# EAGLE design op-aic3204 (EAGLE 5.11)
PID: 827
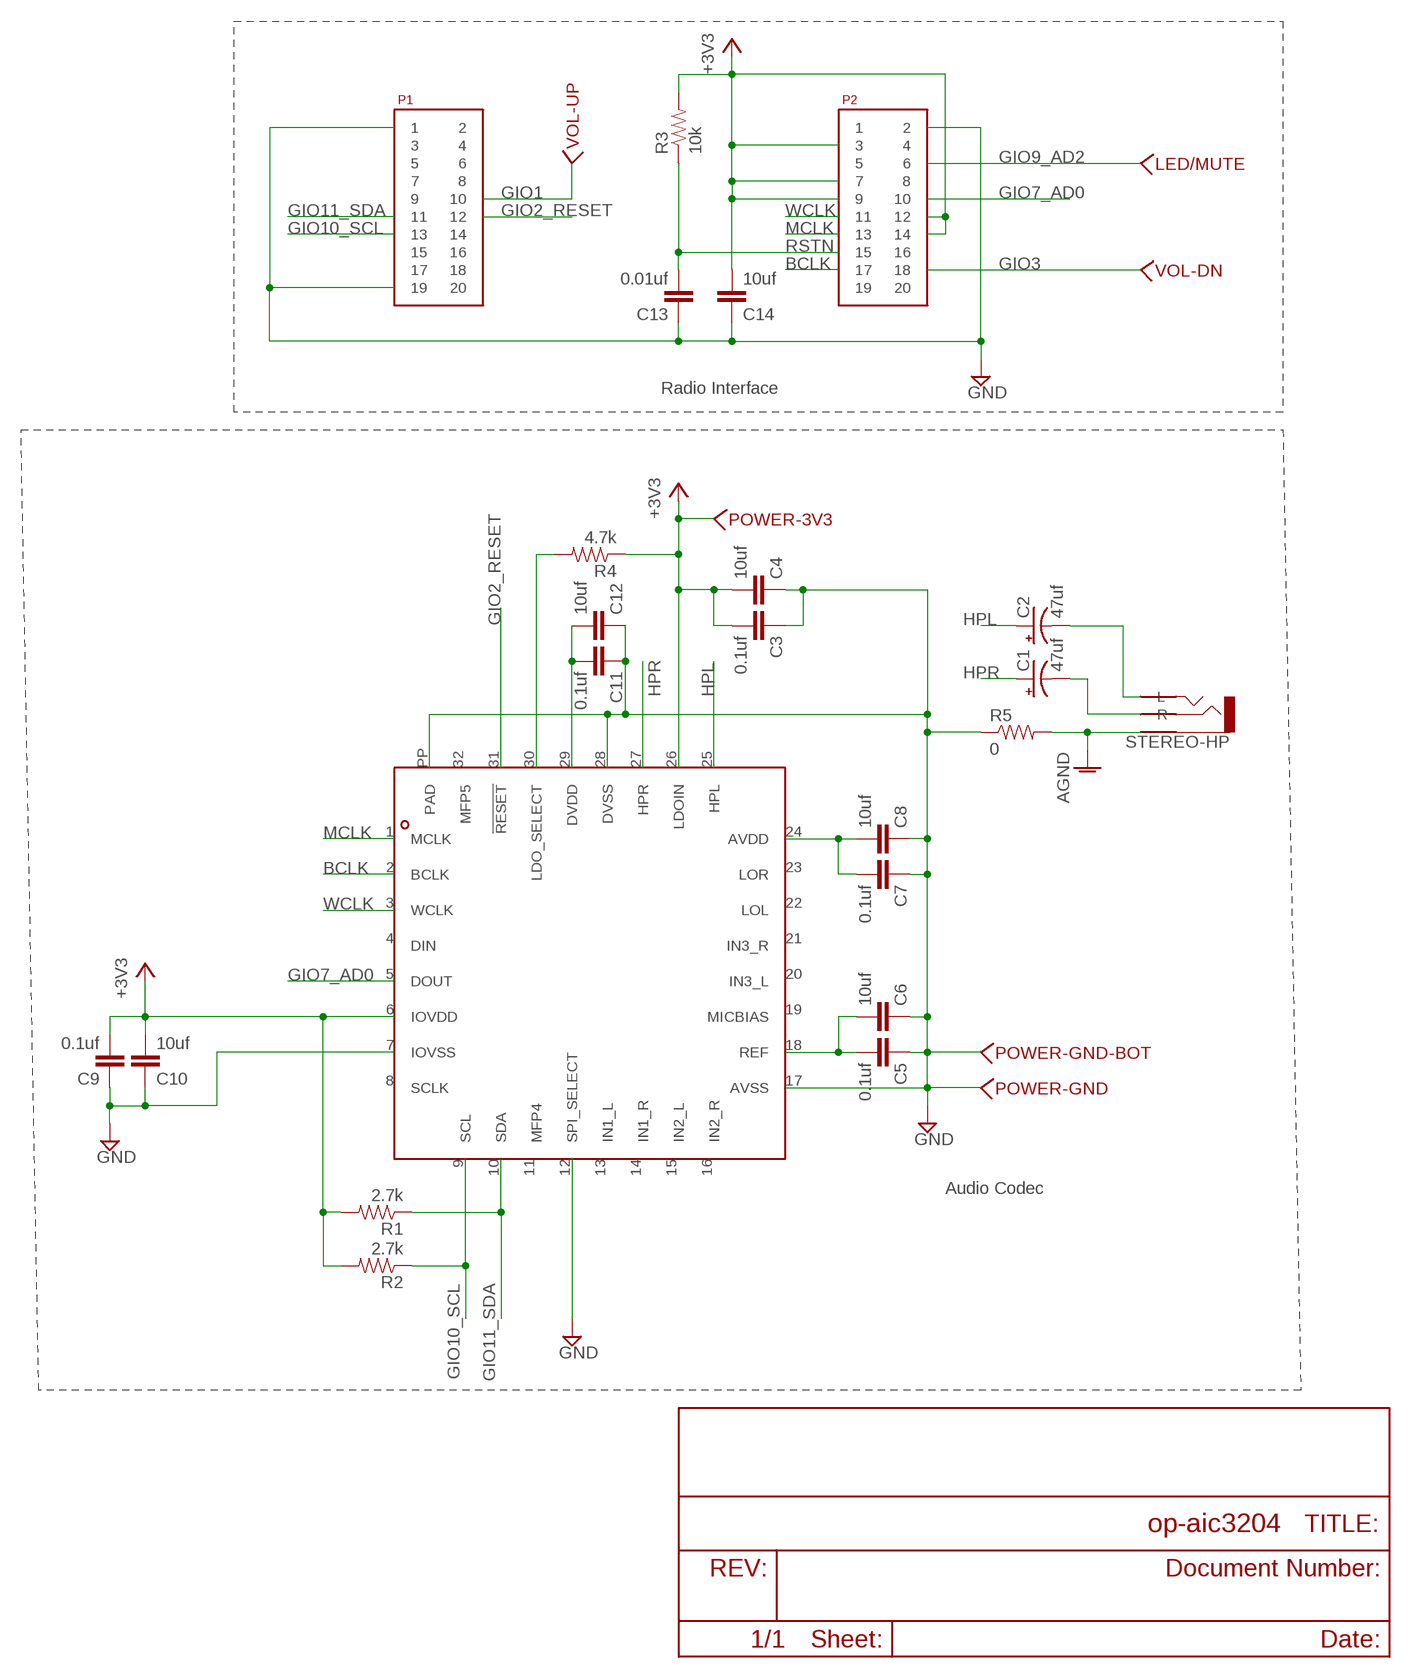
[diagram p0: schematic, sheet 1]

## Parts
C1  47uf  CPOL-USD  [PANASONIC_D]
C2  47uf  CPOL-USD  [PANASONIC_D]
C3  0.1uf  C-EUC0805  [C0805]
C4  10uf  C-EUC0805  [C0805]
C5  0.1uf  C-EUC0805  [C0805]
C6  10uf  C-EUC0805  [C0805]
C7  0.1uf  C-EUC0805  [C0805]
C8  10uf  C-EUC0805  [C0805]
C9  0.1uf  C-EUC0805  [C0805]
C10  10uf  C-EUC0805  [C0805]
C11  0.1uf  C-EUC0805  [C0805]
C12  10uf  C-EUC0805  [C0805]
C13  0.01uf  C-EUC1206  [C1206]
C14  10uf  C-EUC0805  [C0805]
LED/MUTE  WIREPAD-SMD-SMALL-NAMED  [WIREPAD-SMD-SMALL]
P1  SAMTEC-10X2  [SAMTEC-10X2]
P2  SAMTEC-10X2  [SAMTEC-10X2]
POWER-3V3  WIREPAD-SMD-SMALL-NAMED  [WIREPAD-SMD-SMALL]
POWER-GND  WIREPAD-SMD-SMALL-NAMED  [WIREPAD-SMD-SMALL]
POWER-GND-BOT  WIREPAD-SMD-SMALL-NAMED  [WIREPAD-SMD-SMALL]
R1  2.7k  RESISTOR1206  [1206]
R2  2.7k  RESISTOR1206  [1206]
R3  10k  RESISTOR  [0805]
R4  4.7k  RESISTOR1206  [1206]
R5  0  RESISTOR1206  [1206]
STEREO-HP  AUDIO-JACK-STEREO-3PIN948  [AUDIO-JACK-STEREO-3PIN-948]
U$1  AIC3204  [32QFN-AIC3101]
VOL-DN  WIREPAD-SMD-SMALL-NAMED  [WIREPAD-SMD-SMALL]
VOL-UP  WIREPAD-SMD-SMALL-NAMED  [WIREPAD-SMD-SMALL]

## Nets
+3V3: C3.2 C4.2 C9.2 C10.2 C14.2 P2.3 P2.7 P2.9 P2.12 P2.14 POWER-3V3.1 R1.2 R2.2 R3.2 R4.1 U$1.6(IOVDD) U$1.26(LDOIN)
AGND: R5.2 STEREO-HP.1(COM)
BCLK: P2.17 U$1.2(BCLK)
GIO1: P1.10 VOL-UP.1
GIO2_RESET: P1.12 U$1.31(!RESET)
GIO3: P2.18 VOL-DN.1
GIO7_AD0: P2.10 U$1.5(DOUT)
GIO9_AD2: LED/MUTE.1 P2.6
GIO10_SCL: P1.13 R2.1 U$1.9(SCL)
GIO11_SDA: P1.11 R1.1 U$1.10(SDA)
GND: C3.1 C4.1 C5.1 C6.1 C7.1 C8.1 C9.1 C10.1 C11.1 C12.1 C13.1 C14.1 P1.1 P1.19 P2.2 POWER-GND-BOT.1 POWER-GND.1 R5.1 U$1.7(IOVSS) U$1.12(SPI_SELECT) U$1.17(AVSS) U$1.28(DVSS) U$1.PP(PAD)
HPL: C2.+ U$1.25(HPL)
HPR: C1.+ U$1.27(HPR)
MCLK: P2.13 U$1.1(MCLK)
N$1: C2.- STEREO-HP.2(L)
N$2: R4.2 U$1.30(LDO_SELECT)
N$4: C11.2 C12.2 U$1.29(DVDD)
N$8: C1.- STEREO-HP.3(R)
N$10: C7.2 C8.2 U$1.24(AVDD)
N$17: C5.2 C6.2 U$1.18(REF)
RSTN: C13.2 P2.15 R3.1
WCLK: P2.11 U$1.3(WCLK)
Unconnected: P1.2 P1.3 P1.4 P1.5 P1.6 P1.7 P1.8 P1.9 P1.14 P1.15 P1.16 P1.17 P1.18 P1.20 P2.1 P2.4 P2.5 P2.8 P2.16 P2.19 P2.20 U$1.4(DIN) U$1.8(SCLK) U$1.11(MFP4) U$1.13(IN1_L) U$1.14(IN1_R) U$1.15(IN2_L) U$1.16(IN2_R) U$1.19(MICBIAS) U$1.20(IN3_L) U$1.21(IN3_R) U$1.22(LOL) U$1.23(LOR) U$1.32(MFP5)

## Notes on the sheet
- Radio Interface
- Audio Codec

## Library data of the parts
C1 C2 = rcl:CPOL-US: POLARIZED CAPACITOR, American symbol
C3-C14 = rcl:C-EU: CAPACITOR, European symbol
LED/MUTE POWER-3V3 POWER-GND POWER-GND-BOT VOL-DN VOL-UP = trl:WIREPAD-SMD-SMALL-NAMED
P1 P2 = trl:SAMTEC-10X2
R1-R5 = SparkFun:RESISTOR: Resistor
STEREO-HP = trl:AUDIO-JACK-STEREO-3PIN
U$1 = trl:AIC3204

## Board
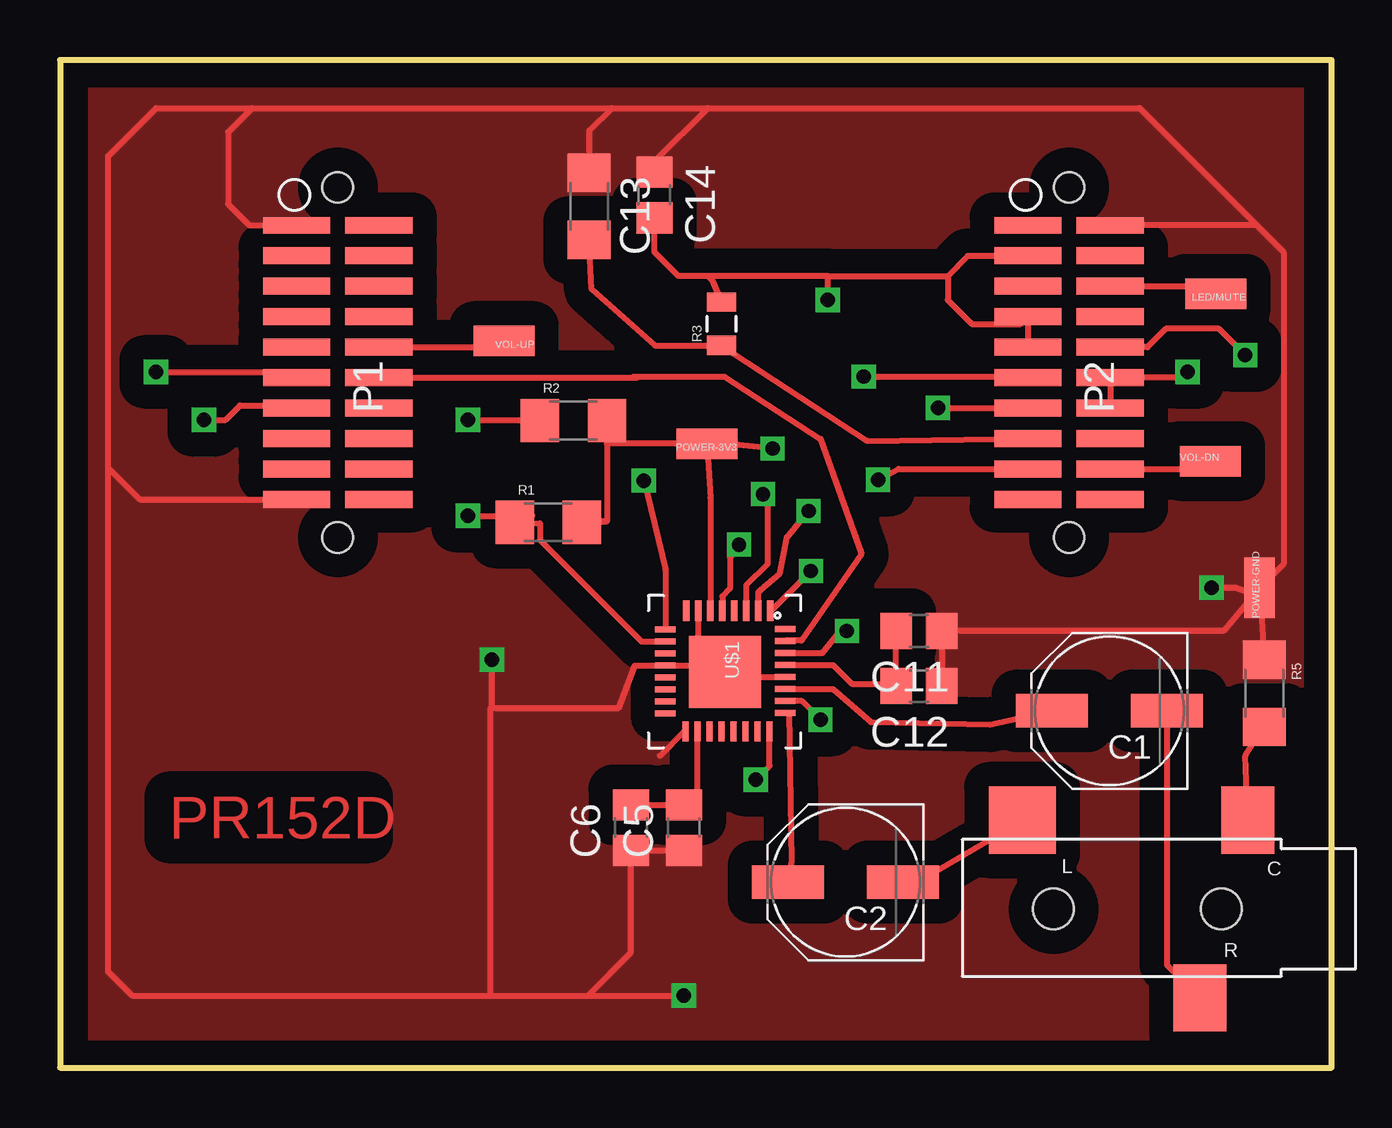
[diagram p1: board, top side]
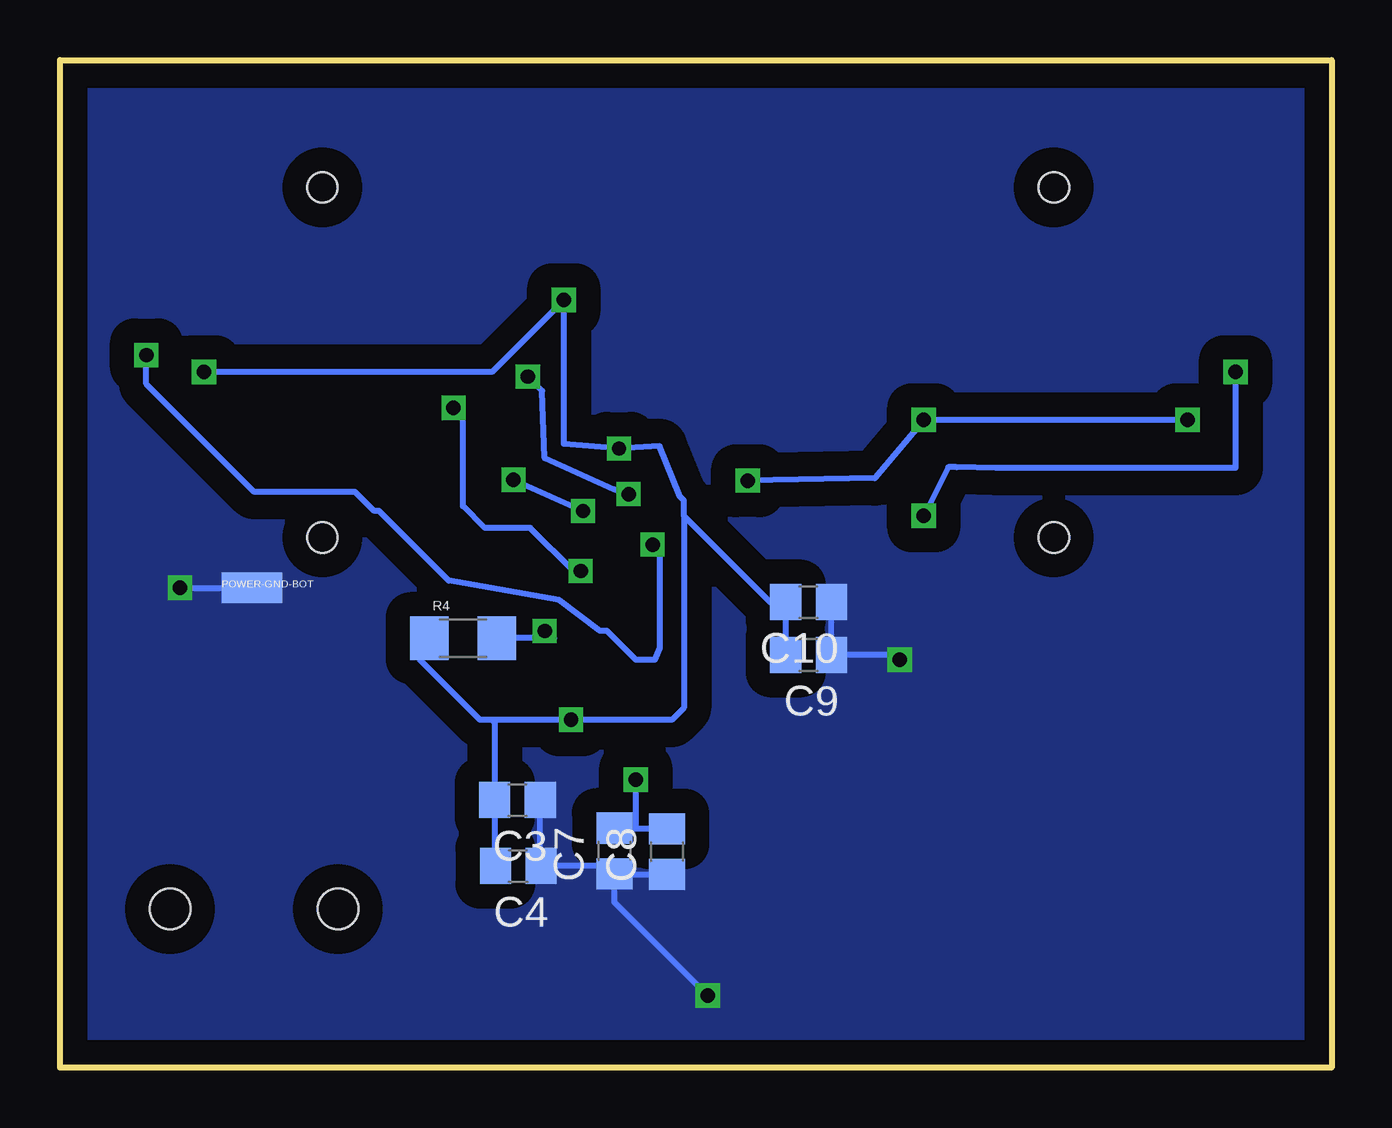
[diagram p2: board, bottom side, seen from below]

Size 53 x 42 mm. Coordinates in mm from the lower left corner, seen from the top.
Outline: 0,0 53,0 53,42 0,42 0,0
Copper layers (1*16): Top 0.035mm / dielectric 1.5mm / Bottom 0.035mm
Design rules "default": minimum track width 10mil, minimum drill 24mil, track to track 8mil, track to pad 8mil, pad to pad 8mil, via to via 8mil, smd to smd 8mil, copper to edge 40mil, drill to drill 8mil, minimum pad ring 10mil, minimum via ring 8mil, stop-mask expansion 4mil, vias tented up to drill 0mil, thermal gap 10mil

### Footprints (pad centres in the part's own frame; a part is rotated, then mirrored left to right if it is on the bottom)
PANASONIC_D = smd 3 x 1.4: + 2.4,0; - -2.4,0
C0805 = smd 1.3 x 1.5: 1 -0.95,0; 2 0.95,0
C1206 = smd 1.6 x 1.8: 1 -1.4,0; 2 1.4,0
WIREPAD-SMD-SMALL = smd 2.54 x 1.27: 1 0,0
SAMTEC-10X2 = smd 0.7 x 2.8: 1 -6.358,-1.296; 2 -6.358,2.134; 3 -5.088,-1.296; 4 -5.088,2.134; 5 -3.818,-1.296; 6 -3.818,2.134; 7 -2.548,-1.296; 8 -2.548,2.134; 9 -1.278,-1.296; 10 -1.278,2.134; 11 -0.008,-1.296; 12 -0.008,2.134; 13 1.262,-1.296; 14 1.262,2.134; 15 2.532,-1.296; 16 2.532,2.134; 17 3.802,-1.296; 18 3.802,2.134; 19 5.072,-1.296; 20 5.072,2.134 | hole 1.27: -7.938,0.42; 6.66,0.42
1206 = smd 1.6 x 1.8: 1 -1.4,0; 2 1.4,0
0805 = smd 0.8 x 1.2: 1 -0.9,0; 2 0.9,0
AUDIO-JACK-STEREO-3PIN-948 = smd 2.2 x 2.8: 1 -3.81,-3.81; 3 -1.81,3.59 | smd 2.8 x 2.8: 2 5.59,-3.81 | hole 1.7: -2.71,-0.11; 4.29,-0.11
32QFN-AIC3101 = smd 0.85 x 0.254: 1 -2.54,1.905; 2 -2.54,1.405; 3 -2.54,0.905; 4 -2.54,0.405; 5 -2.54,-0.095; 6 -2.54,-0.595; 7 -2.54,-1.095; 8 -2.54,-1.595; 17 2.49,-1.625; 18 2.49,-1.125; 19 2.49,-0.625; 20 2.49,-0.125; 21 2.49,0.375; 22 2.49,0.875; 23 2.49,1.375; 24 2.49,1.875 | smd 0.254 x 0.85: 9 -1.76,-2.465; 10 -1.26,-2.465; 11 -0.76,-2.465; 12 -0.26,-2.465; 13 0.24,-2.465; 14 0.74,-2.465; 15 1.24,-2.465; 16 1.74,-2.465; 25 1.72,2.535; 26 1.22,2.535; 27 0.72,2.535; 28 0.22,2.535; 29 -0.28,2.535; 30 -0.78,2.535; 31 -1.28,2.535; 32 -1.78,2.535 | smd 3 x 3: PP 0.02,0.025

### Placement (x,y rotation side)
C1  43.74,14.87 180 top
C2  32.74,7.73 180 top
C3  33.93,11.15 180 bottom
C4  33.9,8.4 180 bottom
C5  26,10 90 top
C6  23.8,10 90 top
C7  29.89,9.03 90 bottom
C8  27.7,9 90 bottom
C9  21.8,17.2 180 bottom
C10  21.8,19.4 180 bottom
C11  35.8,18.2 180 top
C12  35.8,15.9 180 top
C13  22.06,35.9 270 top
C14  24.77,36.37 270 top
LED/MUTE  48.17,32.26 180 top
P1  11.16,28.75 270 top
P2  41.64,28.75 270 top
POWER-3V3  26.97,26.01 180 top
POWER-GND  50,20 90 top
POWER-GND-BOT  45,20 0 bottom
R1  20.36,22.73 0 top
R2  21.4,26.97 0 top
R3  27.58,31 90 top
R4  36.2,17.9 0 bottom
R5  50.2,15.6 270 top
STEREO-HP  45.7,6.5 180 top
U$1  27.7,16.5 270 top
VOL-DN  47.94,25.28 0 top
VOL-UP  18.51,30.29 180 top

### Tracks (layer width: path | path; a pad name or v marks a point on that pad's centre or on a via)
+3V3  (via drill 0.6)
  Top 0.254: P2.3 37.84,33.84 37,33 | 37,33 37,32 38,31 40.05,31 P2.7 P2.9 | P2.14 P2.12 46.76,28.76 v47,29 | C14.2 24.77,34 25.77,33 27,33 | 32,33 27,33 | 32,33 37,33 | R3.2 27.18,32.82 27,33 | v32,32 32,33 | POWER-3V3.1 27.71,26.01 v29.7,25.8 | U$1.6 27.11,23.75 POWER-3V3.1 | 22.75,22.75 R1.2 22.8,22.78 22.8,26 | U$1.26 30.92,15.28 v31.7,14.5 | 22.8,26 R2.2 | POWER-3V3.1 22.81,26.01 22.8,26
  Bottom 0.254: v47,29 35,29 v32,32 32,26 v29.7,25.8 28.01,25.91 27.17,23.81 27,23.64 27,23 | 27,23 27,15 27.5,14.5 v31.7,14.5 35,14.5 | 35,14.5 35.5,14.5 38,17 38,17.5 R4.1 | C4.2 34.88,8.43 C3.2 34.88,14.38 35,14.5 | C9.2 C10.2 23.4,19.4 27,23
AGND
  Top 0.254: STEREO-HP.1 49.41,13.01 R5.2
BCLK  (via drill 0.6)
  Top 0.254: P2.17 34.95,24.95 v34.1,24.5 | v31.2,23.2 30.3,22.1 30,20.6 29.2,19.9 29.11,19.8 U$1.2
  Bottom 0.254: v34.1,24.5 33.9,24.4 v31.2,23.2
GIO1
  Top 0.254: P1.10 18.25,30.03 VOL-UP.1
GIO2_RESET
  Top 0.254: P1.12 24.04,28.76 23.9,28.8 27.7,28.8 31.7,26.2 33.4,21.4 30.9,17.8 30.25,17.8 U$1.31
GIO3
  Top 0.254: P2.18 48.61,24.95 VOL-DN.1
GIO7_AD0  (via drill 0.6)
  Top 0.254: P2.10 45.33,30.03 46.1,30.8 48.3,30.8 v49.4,29.7 | U$1.5 27.61,19.64 27.92,19.96 27.92,21.27 28.02,21.37 28.02,21.52 v28.3,21.8
  Bottom 0.254: v49.4,29.7 49.4,28.5 44.9,24 40.7,24 39.9,23.2 39.7,23.2 36.8,20.3 32.2,19.5 30.5,18.2 30.2,18.2 29,17 28.2,17 28,17.5 28,21.5 v28.3,21.8 28.1,21.6
GIO9_AD2
  Top 0.254: P2.6 46.86,32.57 LED/MUTE.1
GIO10_SCL  (via drill 0.6)
  Top 0.254: v6,27 6.9,27 7.5,27.6 9.75,27.6 P1.13 | v17,27 19.98,27 R2.1 | U$1.9 25.23,20.77 v24.34,24.46
  Bottom 0.254: v6,27 v17,27 19.04,24.57 v24.34,24.46
GIO11_SDA  (via drill 0.6)
  Top 0.254: v4,29 9.62,29 P1.11 | U$1.10 24.24,17.76 20,22 20,22.68 R1.1 19.68,23 v17,23
  Bottom 0.254: v4,29 4,25 14,25 15.63,25.03 15.97,25.03 v17,23
GND  (via drill 0.6)
  Top 0.254: 25,37.55 C14.1 24.77,37.77 27,40 | POWER-GND.1 R5.1 | v48,20 49,20 49.8,19.7 POWER-GND.1 | 49.89,35.11 P2.2 | 49.89,35.11 51,34 51,21 POWER-GND.1 | 27,40 45,40 49.89,35.11 | C13.1 22.06,39.06 23,40 | 23,40 27,40 | P1.1 7.89,35.11 7,36 7,39 8,40 | 8,40 23,40 | P1.19 3.32,23.68 2,25 | 2,25 2,38 4,40 8,40 | U$1.7 26.61,17.6 U$1.PP | U$1.PP 27.45,16.76 U$1.12 23.96,16.76 23.3,15 18,15 | U$1.28 27.93,16.28 U$1.PP | C5.1 C6.1 23.8,4.8 22,3 | 18,3 3,3 2,4 2,25 | 18,3 22,3 | 22,3 v26,3 | 17.95,15 17.95,3.05 18,3 | 17.95,15 18,15 | C12.1 C11.1 48.5,18.2 POWER-GND.1 | 17.95,15 18,15.05 | 18,15 v18,17 | U$1.17 26.01,14.01 25,13
  Bottom 0.254: v48,20 POWER-GND-BOT.1 | C8.1 29.86,8.05 C7.1 | C7.1 29.89,6.89 v26,3 | C3.1 32.98,8.43 C4.1 30.21,8.4 C7.1 | C10.1 C9.1 18.2,17.2 v18,17
  pour Top (isolate 1.016, no thermals): 0,42 53,42 53,0 0,0
  pour Bottom (isolate 1.016, no thermals): 0,42 53,42 53,0 0,0
HPL
  Top 0.254: U$1.25 30.23,14.77 30.4,14.8 30.5,8.58 C2.+
HPR
  Top 0.254: U$1.27 32.22,15.78 33.8,14.4 38.77,14.3 C1.+
MCLK  (via drill 0.6)
  Top 0.254: U$1.1 29.64,19.04 v31.3,20.7 | v36.6,27.5 P2.13
  Bottom 0.254: v31.3,20.7 31.6,20.7 33.4,22.5 35.3,22.5 36.2,23.4 36.2,27.1 v36.6,27.5
N$1
  Top 0.254: STEREO-HP.2 35.36,7.51 C2.-
N$2  (via drill 0.6)
  Top 0.254: U$1.30 31.78,17.28 32.55,18.25 v32.8,18.2
  Bottom 0.254: R4.2 32.4,17.9 v32.8,18.2
N$4
  Top 0.254: U$1.29 32.22,16.78 33,16 34.75,16 C12.2 C11.2
N$8
  Top 0.254: C1.- 46.14,4.28 STEREO-HP.3
N$10  (via drill 0.6)
  Top 0.254: U$1.24 29.57,12.57 v29,12
  Bottom 0.254: C8.2 29,9.95 | 29,9.95 29.86,9.95 C7.2 | 29,9.95 v29,12
N$17
  Top 0.254: U$1.18 26.57,11.53 C5.2 C6.2
RSTN
  Top 0.254: C13.2 22.16,32.44 24.8,30.1 R3.1 33.66,26.12 P2.15
WCLK  (via drill 0.6)
  Top 0.254: U$1.3 28.61,20.11 29.5,21 29.5,23.5 v29.3,23.9 | v33.5,28.8 40.3,28.8 P2.11
  Bottom 0.254: v29.3,23.9 29.9,24.1 32.8,25.4 32.9,28.2 v33.5,28.8

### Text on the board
Top: PR152D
